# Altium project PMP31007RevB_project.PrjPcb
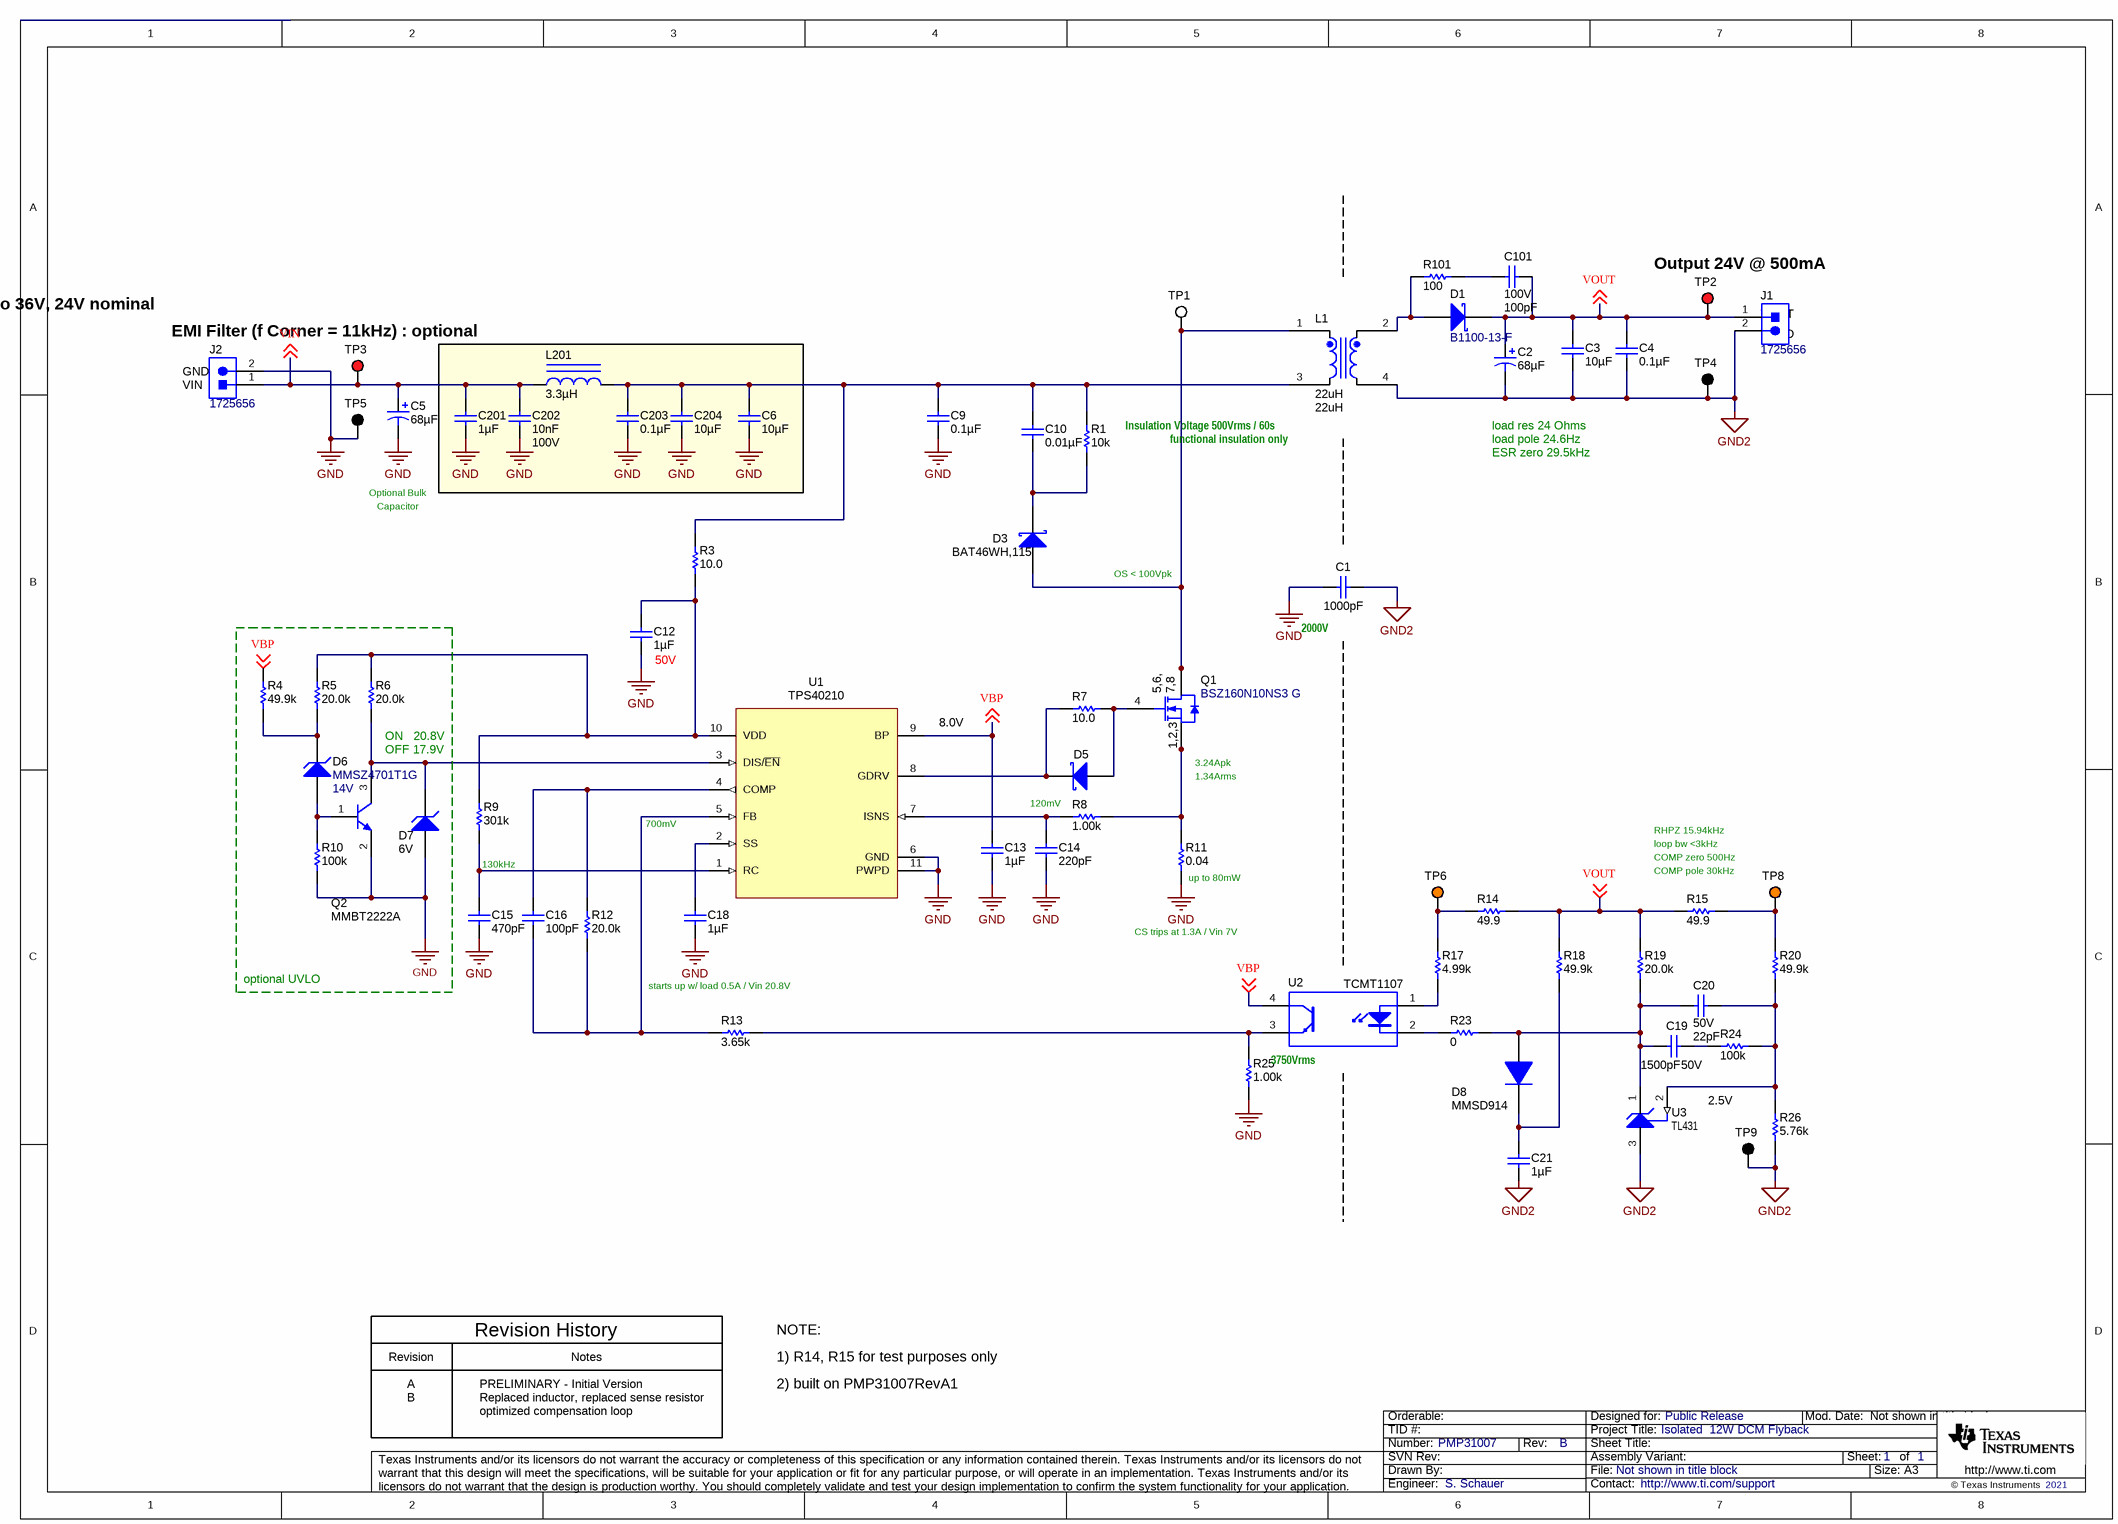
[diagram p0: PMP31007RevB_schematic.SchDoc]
CopyrightYear: 2021; PCB_Layout: S. Schauer; PCB_Rev: A1; PRJ_Customer: Public Release; PRJ_Engineer: S. Schauer; PRJ_Number: PMP31007; PRJ_Title: Isolated  12W DCM Flyback; SCH_Rev: B; TechSupport: http://www.ti.com/support
1 sheet, 68 parts. Net scope: global (net labels, ports and power ports of the same name join across sheets).
Board file: PMP31007RevA1_board.PcbDoc

## Sheet PMP31007RevB_schematic.SchDoc
size A3; Date: Not shown in title block; ApprovedBy: Not shown in title block; CheckedBy: Not shown in title block; Author: Not shown in title block; CompanyName: Not shown in title block; Engineer: Not shown in title block; Organization: Not shown in title block; Address1: Not shown in title block; Address2: Not shown in title block; Address3: Not shown in title block; Address4: Not shown in title block; DocumentNumber: 1; Revision: Use project parameter SCH_Rev; SheetNumber: 1; SheetTotal: 1; PageSetup: Record=PageOptions¦CenterHorizontal=True¦CenterVertical=True¦PrintScale=0.68¦XCorrection=1.00¦YCorrection=1.00¦PrintKind=0¦BorderSize=5000000¦LeftOffset=0¦BottomOffset=0¦Orientation=2¦PaperLength=1000¦PaperWidth=1000¦Scale=100¦PaperSource=15¦PrintQuality=600¦MediaType=1¦DitherType=10¦PrintScaleMode=1¦PaperKind=A4¦PaperIndex=9

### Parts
C1  ValueDisplayed: 1000pF  [1206_180]  (hidden comment: C1206C102KGRACAUTO)
C2  ValueDisplayed: 68µF  [SM_RADIAL_8MM]  (hidden comment: EEHZA1H680P)
C3  ValueDisplayed: 10µF  [1210_270]  (hidden comment: GRM32ER71H106KA12L)
C4  ValueDisplayed: 0.1µF  [0603]  (hidden comment: GCM188R71H104KA57D)
C5  ValueDisplayed: 68µF  [SM_RADIAL_8MM]  (hidden comment: EEHZA1H680P)
C6  ValueDisplayed: 10µF  [1210_270]  (hidden comment: GRM32ER71H106KA12L)
C9  ValueDisplayed: 0.1µF  [0603]  (hidden comment: GCM188R71H104KA57D)
C10  ValueDisplayed: 0.01µF  [0805_HV]  (hidden comment: GRM21BR72A103MA01L)
C12  ValueDisplayed: 1µF  Value2: 50V  [0603]  (hidden comment: UMK107AB7105KA-T)
C13  ValueDisplayed: 1µF  [0603]  (hidden comment: GRM188R71C105KA12D)
C14  ValueDisplayed: 220pF  [0603]  (hidden comment: GRM188R71H221KA01D)
C15  ValueDisplayed: 470pF  [0603]  (hidden comment: GRM1885C1H471JA01D)
C16  ValueDisplayed: 100pF  [0603]  (hidden comment: GRM1885C1H101JA01D)
C18  ValueDisplayed: 1µF  [0603]  (hidden comment: GRM188R71C105KA12D)
C19  VDC_V: 50V  ValueDisplayed: 1500pF  [0603]  (hidden comment: GRM1885C1H152JA01D)
C20  VDC_V: 50V  ValueDisplayed: 22pF  [0603]  (hidden comment: GRM1885C1H220JA01D)
C21  ValueDisplayed: 1µF  [0603]  (hidden comment: GRM188R71C105KA12D)
C101  VDC_V: 100V  ValueDisplayed: 100pF  [0805_HV]  (hidden comment: GRM2165C2A101JA01D)
C201  ValueDisplayed: 1µF  [0805_HV]  (hidden comment: GRM21BR71H105KA12L)
C202  Cap_F: 10nF  VDC_V: 100V  [0603]  (hidden comment: 885012206114)
C203  ValueDisplayed: 0.1µF  [0603]  (hidden comment: GCM188R71H104KA57D)
C204  ValueDisplayed: 10µF  [1210_270]  (hidden comment: GRM32ER71H106KA12L)
D1  B1100-13-F  [SMA]
D3  BAT46WH,115  [SOD-123F]
D5  BAT54LP-7  [X1-DFN1006-2]  (value not drawn)
D6  MMSZ4701T1G  value 14V  [SOD-123]
D7  value 6V  [SOD-323]  (hidden comment: MMSZ5233BS-7-F)
D8  MMSD914  [SOD-123]
J1  1725656  [CONN_1725656]
J2  1725656  [CONN_1725656]
L1  value 22uH  [MSD1278]  (hidden comment: MSD1278-223ML)
L201  ValueDisplayed: 3.3µH  [XEL4030_310]  (hidden comment: XEL4030-332MEB)
Q1  BSZ160N10NS3 G  [PG-TSDSON-8]
Q2  MMBT2222A  [SOT-23]
R1  ValueDisplayed: 10k  [1206]  (hidden comment: CRCW120610K0JNEA)
R3  ValueDisplayed: 10.0  [0603]  (hidden comment: CRCW060310R0FKEA)
R4  ValueDisplayed: 49.9k  [0603]  (hidden comment: CRCW060349K9FKEA)
R5  ValueDisplayed: 20.0k  [0603]  (hidden comment: CRCW060320K0FKEA)
R6  ValueDisplayed: 20.0k  [0603]  (hidden comment: CRCW060320K0FKEA)
R7  ValueDisplayed: 10.0  [0603]  (hidden comment: CRCW060310R0FKEA)
R8  ValueDisplayed: 1.00k  [0603]  (hidden comment: CRCW06031K00FKEA)
R9  ValueDisplayed: 301k  [0603]  (hidden comment: CRCW0603301KFKEA)
R10  value 100k  [0603]  (hidden comment: CRCW0603100KFKEA)
R11  ValueDisplayed: 0.04  [WSL0805]  (hidden comment: WSL0805R0400FEA)
R12  ValueDisplayed: 20.0k  [0603]  (hidden comment: CRCW060320K0FKEA)
R13  ValueDisplayed: 3.65k  [0603]  (hidden comment: CRCW06033K65FKEA)
R14  ValueDisplayed: 49.9  [0603]  (hidden comment: CRCW060349R9FKEA)
R15  ValueDisplayed: 49.9  [0603]  (hidden comment: CRCW060349R9FKEA)
R17  ValueDisplayed: 4.99k  [0603]  (hidden comment: CRCW06034K99FKEA)
R18  ValueDisplayed: 49.9k  [0603]  (hidden comment: CRCW060349K9FKEA)
R19  ValueDisplayed: 20.0k  [0603]  (hidden comment: CRCW060320K0FKEA)
R20  ValueDisplayed: 49.9k  [0603]  (hidden comment: CRCW060349K9FKEA)
R23  ValueDisplayed: 0  [0603]  (hidden comment: CRCW06030000Z0EA)
R24  ValueDisplayed: 100k  [0603]  (hidden comment: CRCW0603100KFKEA)
R25  ValueDisplayed: 1.00k  [0603]  (hidden comment: CRCW06031K00FKEA)
R26  ValueDisplayed: 5.76k  [0603]  (hidden comment: CRCW06035K76FKEA)
R101  ValueDisplayed: 100  [1206]  (hidden comment: CRCW1206100RJNEA)
TP1  5002  [Keystone5002]  (value not drawn)
TP2  5000  [Keystone5000]  (value not drawn)
TP3  5000  [Keystone5000]  (value not drawn)
TP4  5001  [Keystone5001]  (value not drawn)
TP5  5001  [Keystone5001]  (value not drawn)
TP6  5003  [Keystone5003]  (value not drawn)
TP8  5003  [Keystone5003]  (value not drawn)
TP9  5001  [Keystone5001]  (value not drawn)
U1  TPS40210  [DGQ0010D_N]
U2  TCMT1107  [SOP-4]
U3  TL431  [DBZ0003A_N]

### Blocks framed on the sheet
EMI Filter (f Corner = 11kHz) : optional: C6 C201-C204 L201

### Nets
GND: C1.2 C5.2(-) C6.2 C9.2 C12.2 C13.2 C14.2 C15.2 C18.2 C201.2 C202.2 C203.2 C204.2 D7.2(A) J2.2 Q2.2(E) R10.1 R11.1 R25.1 TP5.1 U1.6(GND) U1.11(PWPD)
GND2: C1.1 C2.2(-) C3.2 C4.2 C21.2 J1.2 L1.4 R26.1 TP4.1 TP9.1 U3.3(ANODE)
VBP: C13.1 R4.2 U1.9(BP) U2.4(C) ; off-sheet VBP
VIN: C5.1(+) C201.1 C202.1 J2.1 L201.1 TP3.1 ; off-sheet VIN
VOUT: C2.1(+) C3.1 C4.1 C101.1 D1.1(K) J1.1 R14.2 R15.1 R18.2 R19.2 TP2.1 ; off-sheet VOUT
NetC6_1: C6.1 C9.1 C10.1 C203.1 C204.1 L1.3 L201.2 R1.2 R3.2
NetC10_2: C10.2 D3.1(K) R1.1
NetC12_1: C12.1 R3.1 R5.2 R6.2 R9.2 U1.10(VDD)
NetC14_1: C14.1 R8.1 U1.7(ISNS)
NetC15_1: C15.1 R9.1 U1.1(RC)
NetC16_1: C16.1 R12.2 U1.4(COMP)
NetC16_2: C16.2 R12.1 R13.2 U1.5(FB)
NetC18_1: C18.1 U1.2(SS)
NetC19_1: C19.1 R24.1
NetC19_2: C19.2 C20.1 D8.2(A) R19.1 R23.1 U3.1(CATHODE)
NetC20_2: C20.2 R20.1 R24.2 R26.2 U3.2(REF)
NetC21_1: C21.1 D8.1(K) R18.1
NetC101_2: C101.2 R101.2
NetD1_2: D1.2(A) L1.2 R101.1
NetD3_2: D3.2(A) L1.1 Q1.5(D) Q1.6(D) Q1.7(D) Q1.8(D) Q1.9(D) TP1.1
NetD5_1: D5.1(K) R7.2 U1.8(GDRV)
NetD5_2: D5.2(A) Q1.4(G) R7.1
NetD6_1: D6.1(K) R4.1 R5.1
NetD6_2: D6.2(A) Q2.1(B) R10.2
NetD7_1: D7.1(K) Q2.3(C) R6.1 U1.3(DIS/~{EN})
NetQ1_1: Q1.1(S) Q1.2(S) Q1.3(S) R8.2 R11.2
NetR13_1: R13.1 R25.2 U2.3(E)
NetR14_1: R14.1 R17.2 TP6.1
NetR15_2: R15.2 R20.2 TP8.1
NetR17_1: R17.1 U2.1(A)
NetR23_2: R23.2 U2.2(K)

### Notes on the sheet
- Output 24V @ 500mA
- Input 18V to 36V, 24V nominal
- (near J1) VOUT
- (near J1) GND
- (near J2) VIN
- (near J2) GND
- (near L1) Insulation Voltage 500Vrms / 60s
- (near L1) functional insulation only
- load res 24 Ohms
- load pole 24.6Hz
- ESR zero 29.5kHz
- Optional Bulk
- Capacitor
- OS < 100Vpk
- (near C1) 2000V
- (near R6) ON   20.8V
- (near U1) 8.0V
- OFF 17.9V
- 120mV
- (near Q1) 3.24Apk
- 1.34Arms
- 130kHz
- 700mV
- (near R11) up to 80mW
- RHPZ 15.94kHz
- loop bw <3kHz
- COMP zero 500Hz
- COMP pole 30kHz
- CS trips at 1.3A / Vin 7V
- optional UVLO
- starts up w/ load 0.5A / Vin 20.8V
- (near U2) 3750Vrms
- 2.5V
- Revision History
- NOTE:
- Revision
- A
- B
- PRELIMINARY - Initial Version
- Replaced inductor, replaced sense resistor
- optimized compensation loop
- Notes
- 1) R14, R15 for test purposes only
- 2) built on PMP31007RevA1

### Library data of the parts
C1 = C1206C102KGRACAUTO: CAP, CERM, 1000 pF, 2000 V,+/- 10%, X7R, AEC-Q200 Grade 1, 1206; Manufacturer: Kemet; Polarized: N; CompType: Capacitor; Value: 1000pF; U/M: EA; Cap_F: 0.000000001; Tolerance_%: 10; VDC_V: 2000; Value2: 2000V; TaMin_C: -55; TaMax_C: 125; Cap_Case: 1206; SizeArea_mm2: 5.12; SizeAreaWB_mm2: 10.92; SizeX_mm: 3.2; SizeY_mm: 1.6; SizeZ_mm: 1.8; AEC Category: Q200; AEC Qualified: Y; AEC Grade: 1
C2 C5 = EEHZA1H680P: CAP, Polymer Hybrid, 68 µF, 50 V,+/- 20%, 30 ohm, 8x10 SMD; Manufacturer: Panasonic; Polarized: Y; CompType: Capacitor; Value: 68uF; U/M: EA; Cap_F: 0.000068; Tolerance_%: 20; Value1: 30 ohm; VDC_V: 50; Value2: 50V; ESR_ohm: 30; IRMS_A: 1.8; TaMin_C: -55; TaMax_C: 105; SizeAreaWB_mm2: 113.3; SizeArea_mm2: 74.7; SizeX_mm: 9; SizeY_mm: 8.3; SizeZ_mm: 10.2; AEC Category: Q200
C3 C6 C204 = GRM32ER71H106KA12L: CAP, CERM, 10 µF, 50 V,+/- 10%, X7R, 1210; Manufacturer: MuRata; Polarized: N; CompType: Capacitor; Value: 10uF; U/M: EA; Cap_F: 0.00001; Tolerance_%: 10; Value1: Unknown; VDC_V: 50; Value2: 50V; TaMin_C: -55; TaMax_C: 125; Cap_Case: 1210; SizeArea_mm2: 8; SizeAreaWB_mm2: 14.7; SizeX_mm: 3.2; SizeY_mm: 2.5; SizeZ_mm: 2.7; AEC Category: Q200; Green_Lifecycle: Active; Green_REACh: Passed
C4 C9 C203 = GCM188R71H104KA57D: CAP, CERM, 0.1 µF, 50 V, +/- 10%, X7R, 0603; Manufacturer: MuRata; Polarized: N; CompType: Capacitor; Value: 0.1uF; U/M: EA; Cap_F: 0.0000001; Tolerance_%: 10; ESR_ohm: 0.02; Value1: 0.02 ohm; VDC_V: 50; Value2: 50V; IRMS_A: 1.84; TaMin_C: -55; TaMax_C: 125; AEC Category: Q200
C10 = GRM21BR72A103MA01L: CAP, CERM, 0.01 µF, 100 V, +/- 20%, X7R, 0805; Manufacturer: MuRata; Polarized: N; CompType: Capacitor; Value: 0.01uF; U/M: EA; Cap_F: 0.00000001; Tolerance_%: 20; Value1: Unknown; VDC_V: 100; Value2: 100V; TaMin_C: -55; TaMax_C: 125; Cap_Case: 0805; SizeArea_mm2: 2.5; SizeAreaWB_mm2: 6.75; SizeX_mm: 2; SizeY_mm: 1.25; SizeZ_mm: 1.45; AEC Category: Q200
C12 = UMK107AB7105KA-T: CAP, CERM, 1 µF, 50 V,+/- 10%, X7R, 0603; Manufacturer: Taiyo Yuden; Polarized: N; CompType: Capacitor; Value: 1uF; U/M: EA; Cap_F: 0.000001; Tolerance_%: 10; VDC_V: 50; TaMin_C: -55; TaMax_C: 125; SizeArea_mm2: 1.28; SizeAreaWB_mm2: 4.68; SizeX_mm: 1.6; SizeY_mm: 0.8; SizeZ_mm: 1; AEC Category: Q200; Green_Lifecycle: Active; Green_REACh: Passed
C13 C21 = GRM188R71C105KA12D: CAP, CERM, 1 µF, 16 V, +/- 10%, X7R, 0603; Manufacturer: MuRata; Polarized: N; CompType: Capacitor; Value: 1uF; U/M: EA; Cap_F: 0.000001; Tolerance_%: 10; ESR_ohm: 0.011; Value1: 0.011 ohm; VDC_V: 16; Value2: 16V; TaMin_C: -55; TaMax_C: 125; AEC Category: Q200
C14 = GRM188R71H221KA01D: CAP, CERM, 220 pF, 50 V,+/- 10%, X7R, 0603; Manufacturer: MuRata; Polarized: N; CompType: Capacitor; Value: 220pF; U/M: EA; Cap_F: 0.00000000022; Tolerance_%: 10; Value1: Unknown; VDC_V: 50; Value2: 50V; TaMin_C: -55; TaMax_C: 125; SizeArea_mm2: 1.28; SizeAreaWB_mm2: 4.68; SizeX_mm: 1.6; SizeY_mm: 0.8; SizeZ_mm: 1; AEC Category: Q200; Green_Lifecycle: Active; Green_REACh: Passed
C15 = GRM1885C1H471JA01D: CAP, CERM, 470 pF, 50 V, +/- 5%, C0G/NP0, 0603; Manufacturer: MuRata; Polarized: N; CompType: Capacitor; Value: 470pF; U/M: EA; Cap_F: 0.00000000047; Tolerance_%: 5; Value1: Unknown; VDC_V: 50; Value2: 50V; TaMin_C: -55; TaMax_C: 125; SizeArea_mm2: 1.28; SizeAreaWB_mm2: 4.68; SizeX_mm: 1.6; SizeY_mm: 0.8; SizeZ_mm: 1; AEC Category: Q200
C16 = GRM1885C1H101JA01D: CAP, CERM, 100 pF, 50 V,+/- 5%, C0G/NP0, 0603; Manufacturer: MuRata; Polarized: N; CompType: Capacitor; Value: 100pF; U/M: EA; Cap_F: 0.0000000001; Tolerance_%: 5; VDC_V: 50; Value2: 50V; TaMin_C: -55; TaMax_C: 125; SizeArea_mm2: 1.28; SizeAreaWB_mm2: 4.68; SizeX_mm: 1.6; SizeY_mm: 0.8; SizeZ_mm: 1; AEC Category: Q200; Green_Lifecycle: Active; Green_REACh: Passed
C18 = GRM188R71C105KA12D: CAP, CERM, 1 µF, 16 V,+/- 10%, X7R, 0603; Manufacturer: MuRata; Polarized: N; CompType: Capacitor; Value: 1uF; U/M: EA; Cap_F: 0.000001; Tolerance_%: 10; ESR_ohm: 0.011; Value1: 0.011 ohm; VDC_V: 16; Value2: 16V; TaMin_C: -55; TaMax_C: 125; SizeArea_mm2: 1.28; SizeAreaWB_mm2: 4.68; SizeX_mm: 1.6; SizeY_mm: 0.8; SizeZ_mm: 1; AEC Category: Q200; Green_Lifecycle: Active; Green_REACh: Passed
C19 = CMP-0007186-4: CAP, CERM, 1500 pF, 50 V, +/- 5%, C0G/NP0, 0603; Manufacturer: MuRata; TaMin_C: -55°C; Polarized: N; SizeAreaWB_mm2: 4.68; Value1: Unknown; U/M: EA; Value: 1500pF; TaMax_C: 125°C; SizeZ_mm: 1; SizeX_mm: 1.6; SizeY_mm: 0.8; SizeArea_mm2: 1.28; Cap_F: 1.5nF; AEC Category: Q200
C20 = CMP-0007196-4: CAP, CERM, 22 pF, 50 V, +/- 5%, C0G/NP0, 0603; Manufacturer: MuRata; TaMin_C: -55°C; Polarized: N; SizeAreaWB_mm2: 4.68; Value1: Unknown; U/M: EA; Value: 22pF; TaMax_C: 125°C; SizeZ_mm: 1; SizeX_mm: 1.6; SizeY_mm: 0.8; SizeArea_mm2: 1.28; AEC Category: Q200
C101 = CMP-0008093-2: CAP, CERM, 100 pF, 100 V, +/- 5%, C0G/NP0, 0805; Manufacturer: MuRata; TaMin_C: -55°C; Polarized: N; SizeAreaWB_mm2: 6.75; Value1: Unknown; U/M: EA; Value: 100pF; TaMax_C: 125°C; SizeZ_mm: 1.45; SizeX_mm: 2; SizeY_mm: 1.25; Cap_Case: 0805; SizeArea_mm2: 2.5; AEC Category: Q200
C201 = GRM21BR71H105KA12L: CAP, CERM, 1 µF, 50 V,+/- 10%, X7R, 0805; Manufacturer: MuRata; Polarized: N; CompType: Capacitor; Value: 1uF; U/M: EA; Cap_F: 0.000001; Tolerance_%: 10; VDC_V: 50; Value2: 50V; TaMin_C: -55; TaMax_C: 125; Cap_Case: 0805; SizeArea_mm2: 2.5; SizeAreaWB_mm2: 6.75; SizeX_mm: 2; SizeY_mm: 1.25; SizeZ_mm: 1.45; AEC Category: Q200; Green_Lifecycle: Active; Green_REACh: Passed
C202 = CMP-0079993-1: CAP, CERM, 0.01 µF, 100 V,+/- 10%, X7R, 0603; Manufacturer: Wurth Elektronik; TaMin_C: -55°C; Polarized: N; SizeAreaWB_mm2: 4.68; U/M: EA; Value: 0.01uF; TaMax_C: 105°C; SizeZ_mm: 1; SizeX_mm: 1.6; SizeY_mm: 0.8; SizeArea_mm2: 1.28; AEC Category: Q200; ValueDisplayed: 0.01µF
D1 = CMP-0028371-2: Diode, Schottky, 100 V, 1 A, SMA; Manufacturer: Diodes Inc.; Io_A: 1A; SizeZ_mm: 2.87; Green_REACh: Passed; TJmax_C: 150°C; Value: 100V; SizeAreaWB_mm2: 37.3428; Vf_V: 790mV; RJC_CperW: 25; SizeX_mm: 5.59; AEC Category: Q101; SizeArea_mm2: 16.3228; SizeY_mm: 2.92; Value2: 0.79V; Green_Lifecycle: Active
D3 = BAT46WH,115: Diode, Schottky, 100 V, 0.25 A, SOD-123F; Manufacturer: Nexperia; U/M: EA; Vf_V: 0.85; Value: 100V; Value1: 0.25A; Value2: 0.85V; Io_A: 0.25; Vr_V: 100; TJmax_C: 150; SizeAreaWB_mm2: 11.7; SizeArea_mm2: 5.6; SizeX_mm: 3.5; SizeY_mm: 1.6; SizeZ_mm: 1.1; AEC Category: Q101; Green_Lifecycle: Not Set; Green_REACh: Incomplete
D5 = BAT54LP-7: Diode, Schottky, 30 V, 0.2 A, 1.00x0.50x0.60mm; Manufacturer: Diodes Inc.; U/M: EA; Vf_V: 1; Value: 30V; Value1: 0.2A; Value2: 1V; Io_A: 0.2; Vr_V: 30; SizeAreaWB_mm2: 3.2; SizeArea_mm2: 0.6; SizeZ_mm: 0.53; AEC Category: Q101; Green_Lifecycle: Not Set; Green_REACh: Incomplete
D6 = CMP-0005744-4: Diode, Zener, 14 V, 500 mW, SOD-123; Manufacturer: ON Semiconductor; Power_W: 500mW; SizeAreaWB_mm2: 13.095; AEC Category: Q101; Value1: 0.5W; SizeY_mm: 1.7; SizeZ_mm: 1.35; RJA_CperW: 340; SizeArea_mm2: 6.545; SizeX_mm: 3.85
D7 = MMSZ5233BS-7-F: Diode, Zener, 6 V, 200 mW, SOD-323; Manufacturer: Diodes Inc.; SymbolCreator: a0412235; U/M: EA; Power_W: 0.2; Vz_V: 6; Value1: 0.2W; RJA_CperW: 350; SizeAreaWB_mm2: 8.695; SizeArea_mm2: 3.645; SizeX_mm: 2.7; SizeY_mm: 1.35; SizeZ_mm: 1; AEC Category: Q101
D8 = MMSD914T1G: Diode, Switching, 100 V, 0.2 A, SOD-123; Manufacturer: ON Semiconductor; U/M: EA; Value: 100V; Value1: 0.2A; Io_A: 0.2; Vr_V: 100; TJmax_C: 150; SizeAreaWB_mm2: 13.095; SizeArea_mm2: 6.545; SizeX_mm: 3.85; SizeY_mm: 1.7; SizeZ_mm: 1.35; AEC Category: Q101
J1 J2 = CMP-0055479-2: Terminal Block, 100mil, 2x1, 6A, 63V, TH; Manufacturer: Phoenix Contact; Green_REACh: Incomplete; CNHeader: FALSE; CT: TRUE; Green_Lifecycle: Not Set
L1 = CMP-0012866-2: Coupled inductor, 22 uH, 6.8 A, 0.096 ohm, TH; Manufacturer: Coilcraft; SizeAreaWB_mm2: 204.49; DCR_ohm: 0.096; SizeZ_mm: 8.05; SizeX_mm: 12.3; SizeArea_mm2: 151.29; Ind_H: 22µH
L201 = XEL4030-332MEB: Inductor, Shielded, 3.3 µH, 5 A, 0.0286 ohm, SMD; Manufacturer: Coilcraft; Value: 3.3uH; Ind_H: 3.3E-6; Imax_A: 5; Irms: 5A @ 20C rise; Isat: 5.9A @ 30% inductance drop; DCR_ohm: 0.0286; Value2: 5A; SizeAreaWB_mm2: 25; SizeArea_mm2: 16; SizeX_mm: 4; SizeZ_mm: 3.1; AEC Category: Q200; AEC Qualified: N
Q1 = CMP-0000952-2: MOSFET, N-CH, 100 V, 28 A, PG-TSDSON-8; Alternate Manufacturer: None; Manufacturer: Infineon Technologies; SizeZ_mm: 1.1; ChType: N; Value2: 19 nC; Value1: 0.02; VdsMax_V: 100V; SizeX_mm: 3.4; Vgs_V: 20V; Value: 100V; Rdson45_ohm: 0.024; SizeArea_mm2: 11.56; AEC Category: Q101; IdsMax_A: 28A; SizeAreaWB_mm2: 19.36; U/M: EA; QgTyp_nC: 19
Q2 = MMBT2222A, Fairchild Semiconductor: Transistor, NPN, 40V, 0.15A, SOT-23; CompType: BJT; PNP: 0; NPN: 1; Vceo_V: 40; Vcesat1_V: 0.3; Value: 0.3V; IcRated_A: 0.15; HfeMax: 300; TaMin_C: -55; TaMax_C: 150; U/M: EA
R1 = CRCW120610K0JNEA: RES, 10 k, 5%, 0.25 W, 1206; Manufacturer: Vishay-Dale; CompType: Resistor; Value: 10k; Res_ohm: 10000; Value_Code: 10k0; Tolerance_%: 5; Power_W: 0.25; Value2: 0.25W; VDC_V: 200; TempCo: 200 ppm/C; SizeArea_mm2: 5.12; SizeX_mm: 3.2; SizeY_mm: 1.6; SizeZ_mm: 1.35; EIA_Code: E24; U/M: EA; AEC Category: Q200
R3 R7 = CRCW060310R0FKEA: RES, 10.0, 1%, 0.1 W, 0603; Manufacturer: Vishay-Dale; CompType: Resistor; Value: 10.0; Res_ohm: 10; Value_Code: 10R0; Tolerance_%: 1; Power_W: 0.1; Value2: 0.1W; VDC_V: 75; TempCo: 100 ppm/C; SizeArea_mm2: 1.28; SizeX_mm: 1.6; SizeY_mm: 0.8; EIA_Code: E96; U/M: EA; AEC Category: Q200
R4 = CMP-0022447-4: RES, 49.9 k, 1%, 0.1 W, AEC-Q200 Grade 0, 0603; Manufacturer: Vishay-Dale; Power_W: 100mW; TempCo: 100 ppm/C; Value_Code: 49k9; Value: 49.9k; EIA_Code: E96; SizeX_mm: 1.6; SizeY_mm: 0.8; SizeZ_mm: 1; Value2: 0.1W; SizeArea_mm2: 1.28; AEC Qualified: Y; VDC_V: 75V; AEC Category: Q200; AEC Grade: 0
R5 R6 = CRCW060320K0FKEA: RES, 20.0 k, 1%, 0.1 W, 0603; Manufacturer: Vishay-Dale; CompType: Resistor; Value: 20.0k; Res_ohm: 20000; Value_Code: 20k0; Tolerance_%: 1; Power_W: 0.1; Value2: 0.1W; VDC_V: 75; TempCo: 100 ppm/C; SizeArea_mm2: 1.28; SizeX_mm: 1.6; SizeY_mm: 0.8; EIA_Code: E96; U/M: EA; AEC Category: Q200; Green_Lifecycle: Active; Green_REACh: Passed
R8 = CRCW06031K00FKEA: RES, 1.00 k, 1%, 0.1 W, 0603; Manufacturer: Vishay-Dale; CompType: Resistor; Value: 1.00k; Res_ohm: 1000; Value_Code: 1k00; Tolerance_%: 1; Power_W: 0.1; Value2: 0.1W; VDC_V: 75; TempCo: 100 ppm/C; EIA_Code: E96; U/M: EA
R9 = CMP-0022320-4: RES, 301 k, 1%, 0.1 W, AEC-Q200 Grade 0, 0603; Manufacturer: Vishay-Dale; Power_W: 100mW; TempCo: 100 ppm/C; Value: 301k; EIA_Code: E96; SizeX_mm: 1.6; SizeY_mm: 0.8; SizeZ_mm: 1; Value2: 0.1W; SizeArea_mm2: 1.28; AEC Qualified: Y; VDC_V: 75V; AEC Category: Q200; AEC Grade: 0
R10 = CRCW0603100KFKEA: RES, 100k ohm, 1%, 0.1W, 0603; Manufacturer: Vishay-Dale; CompType: Resistor; Res_ohm: 100000; Tolerance_%: 1; Power_W: 0.1; VDC_V: 75; TempCo: 100 ppm/C; EIA_Code: E96; U/M: EA
R11 = CMP-0065348-2: RES, 0.04, 1%, .125 W, AEC-Q200 Grade 1, 0805; Manufacturer: Vishay-Dale; Power_W: 125mW; TempCo: 75 ppm/C; Value_Code: R040; U/M: EA; Value: 0.04; SizeX_mm: 2.03; SizeY_mm: 1.27; SizeZ_mm: 0.584; Value2: .125W; SizeArea_mm2: 2.5781; AEC Qualified: Y; AEC Grade: 1; AEC Category: Q200
R12 R19 = CRCW060320K0FKEA: RES, 20.0 k, 1%, 0.1 W, 0603; Manufacturer: Vishay-Dale; CompType: Resistor; Value: 20.0k; Res_ohm: 20000; Value_Code: 20k0; Tolerance_%: 1; Power_W: 0.1; Value2: 0.1W; VDC_V: 75; TempCo: 100 ppm/C; SizeArea_mm2: 1.28; SizeX_mm: 1.6; SizeY_mm: 0.8; EIA_Code: E96; U/M: EA; AEC Category: Q200
R13 = CMP-0022379-4: RES, 3.65 k, 1%, 0.1 W, AEC-Q200 Grade 0, 0603; Manufacturer: Vishay-Dale; Power_W: 100mW; TempCo: 100 ppm/C; Value_Code: 3k65; Value: 3.65k; EIA_Code: E96; SizeX_mm: 1.6; SizeY_mm: 0.8; SizeZ_mm: 1; Value2: 0.1W; SizeArea_mm2: 1.28; AEC Qualified: Y; VDC_V: 75V; AEC Category: Q200; AEC Grade: 0
R14 R15 = CRCW060349R9FKEA: RES, 49.9, 1%, 0.1 W, 0603; Manufacturer: Vishay-Dale; CompType: Resistor; Value: 49.9; Value_Code: 49R9; Tolerance_%: 1; Power_W: 0.1; Value2: 0.1W; VDC_V: 75; TempCo: 100 ppm/C; SizeArea_mm2: 1.28; SizeX_mm: 1.6; SizeY_mm: 0.8; EIA_Code: E96; U/M: EA; AEC Category: Q200
R17 = CRCW06034K99FKEA: RES, 4.99 k, 1%, 0.1 W, 0603; Manufacturer: Vishay-Dale; CompType: Resistor; Value: 4.99k; Res_ohm: 4990; Value_Code: 4k99; Tolerance_%: 1; Power_W: 0.1; Value2: 0.1W; VDC_V: 75; TempCo: 100 ppm/C; SizeArea_mm2: 1.28; SizeX_mm: 1.6; SizeY_mm: 0.8; EIA_Code: E96; U/M: EA; AEC Category: Q200; Green_Lifecycle: Active; Green_REACh: Passed
R18 R20 = CRCW060349K9FKEA: RES, 49.9 k, 1%, 0.1 W, 0603; Manufacturer: Vishay-Dale; CompType: Resistor; Value: 49.9k; Res_ohm: 49900; Value_Code: 49k9; Tolerance_%: 1; Power_W: 0.1; Value2: 0.1W; VDC_V: 75; TempCo: 100 ppm/C; SizeArea_mm2: 1.28; SizeX_mm: 1.6; SizeY_mm: 0.8; EIA_Code: E96; U/M: EA; AEC Category: Q200; Green_Lifecycle: Active; Green_REACh: Passed
R23 = CRCW06030000Z0EA: RES, 0, 5%, 0.1 W, 0603; Manufacturer: Vishay-Dale; CompType: Resistor; Value: 0; Value_Code: 0000; Tolerance_%: 5; Power_W: 0.1; Value2: 0.1W; VDC_V: 75; TempCo: 200 ppm/C; SizeArea_mm2: 1.28; SizeX_mm: 1.6; SizeY_mm: 0.8; SizeZ_mm: 1; EIA_Code: E24; U/M: EA; AEC Category: Q200
R24 = CRCW0603100KFKEA: RES, 100 k, 1%, 0.1 W, 0603; Manufacturer: Vishay-Dale; CompType: Resistor; Value: 100k; Res_ohm: 100000; Tolerance_%: 1; Power_W: 0.1; Value2: 0.1W; VDC_V: 75; TempCo: 100 ppm/C; SizeArea_mm2: 1.28; SizeX_mm: 1.6; SizeY_mm: 0.8; EIA_Code: E96; U/M: EA; AEC Category: Q200
R25 = CRCW06031K00FKEA: RES, 1.00 k, 1%, 0.1 W, 0603; Manufacturer: Vishay-Dale; CompType: Resistor; Value: 1.00k; Res_ohm: 1000; Value_Code: 1k00; Tolerance_%: 1; Power_W: 0.1; Value2: 0.1W; VDC_V: 75; TempCo: 100 ppm/C; SizeArea_mm2: 1.28; SizeX_mm: 1.6; SizeY_mm: 0.8; EIA_Code: E96; U/M: EA; AEC Category: Q200
R26 = CRCW06035K76FKEA: RES, 5.76 k, 1%, 0.1 W, 0603; Manufacturer: Vishay-Dale; CompType: Resistor; Value: 5.76k; Res_ohm: 5760; Value_Code: 5k76; Tolerance_%: 1; Power_W: 0.1; Value2: 0.1W; VDC_V: 75; TempCo: 100 ppm/C; SizeArea_mm2: 1.28; SizeX_mm: 1.6; SizeY_mm: 0.8; EIA_Code: E96; U/M: EA; AEC Category: Q200; Green_Lifecycle: Active; Green_REACh: Passed
R101 = CMP-0018575-3: RES, 100, 5%, 0.25 W, AEC-Q200 Grade 0, 1206; Manufacturer: Vishay-Dale; Power_W: 250mW; TempCo: 200 ppm/C; Value_Code: 100R; Value: 100; EIA_Code: E24; SizeX_mm: 3.2; SizeY_mm: 1.6; SizeZ_mm: 1.35; Value2: 0.25W; SizeArea_mm2: 5.12; AEC Qualified: Y; VDC_V: 200V; AEC Category: Q200; AEC Grade: 0
TP1 = 5002: Test Point, Miniature, White, TH; Manufacturer: Keystone; CompType: Test Point Loop; ContactFinish: Silver
TP2 TP3 = 5000: Test Point, Miniature, Red, TH; Manufacturer: Keystone; CompType: Test Point Loop; U/M: EA
TP4 TP5 TP9 = 5001: Test Point, Miniature, Black, TH; Manufacturer: Keystone; CompType: Test Point Loop; U/M: EA
TP6 TP8 = 5003: Test Point, Miniature, Orange, TH; Manufacturer: Keystone; CompType: Test Point Loop; ContactFinish: Silver
U1 = TPS40210QDGQRQ1: 4.5-V TO 52-V INPUT CURRENT MODE BOOST CONTROLLER, DGQ0010D; PartNumber: TPS40210DGQ; Manufacturer: Texas Instruments; SymbolCreator: a0412235; CompType: IC; U/M: EA
U2 = TCMT1107: Optocoupler, 3.75 kV, 80-160% CTR, SMT; Manufacturer: Vishay-Semiconductor; CTR (Min): 80%; CTR (Max): 160%; Voltage_Isolation_Vrms: 3750V; SizeAreaWB_mm2: 43.65; SizeArea_mm2: 19.95; SizeX_mm: 7; SizeY_mm: 2.85; SizeZ_mm: 2.3
U3 = TL431AIDBZR: Adjustable Precision Shunt Regulator, 34 ppm / degC, 100 mA, -40 to 85 degC, 3-pin SOT-23 (DBZ), Green (RoHS & no Sb/Br); Manufacturer: Texas Instruments; Alternate PartNumber: Equivalent; Initial Accuracy @ 25/deg C(%): 1; Iout/Iz(Max)(mA): 100; Min Iz for Regulation(uA): 600; Rating: Catalog; SubFamily: Shunt Voltage Reference; Temp Coeff(Max)(ppm/ degree C): 92; Temp Coeff(Typ)(ppm/ degree C): 34; VO Adj(Max)(V): 36; VO Adj(Min)(V): 2.495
